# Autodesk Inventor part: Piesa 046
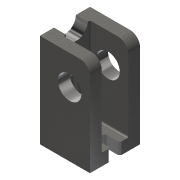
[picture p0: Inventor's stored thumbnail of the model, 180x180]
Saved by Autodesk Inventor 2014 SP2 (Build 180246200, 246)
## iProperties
Created: 2009-01
Part Number: Piesa 046
Document SubType Name: Modeling
Designer: Costel
Material: Steel, Cast
Density: 7.85 g/cm^3
Appearance: Steel - Cast
Mass: 2292.52 g
Surface Area: 500.17 cm^2
Volume: 292.041 cm^3
Author: Costel
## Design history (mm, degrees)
sketch "Sketch2"
  geometry: L1 (-32, 120)-(32, 120); L2 (32, 120)-(32, 0); L3 (32, 0)-(-32, 0); L4 (-32, 0)-(-32, 120); L5 (-38.4, 0)-(51.2, 0) reference; L6 (0, -12)-(0, 156) reference
  constraints: 8 end point, 2 parallel, 1 collinear, 1 horizontal, 1 perpendicular, 1 other
  dimensions: "d0" = 64 distance of L1.start L1.end; "d1" = 120 distance of L3.end L1.start
extrude "Extrusion1" new body sketch "Sketch2" distance "d2" = 15; taper "d3" = 0 deg
sketch "Sketch3"
  geometry: L1 (-120, 32)-(0, 32) reference; L2 (-120, -32)-(-120, 32) reference; L3 (0, -32)-(-120, -32) reference; L4 (0, 32)-(0, -32) reference; L5 (-120, 17)-(-15, 17); L6 (-15, 17)-(-15, -17); L7 (-15, -17)-(-120, -17); L8 (-120, -17)-(-120, -32); L9 (-120, -32)-(0, -32); L10 (0, -32)-(0, 32); L11 (0, 32)-(-120, 32); L12 (-120, 32)-(-120, 17); L13 (12, 0)-(-156, 0) reference
  constraints: 16 end point, 4 perpendicular, 2 point on line, 1 collinear, 1 other
  dimensions: "d4" = 34 distance between parallel lines of L5 L7; "d5" = 15 distance between parallel lines of L4 L6
extrude "Extrusion2" join sketch "Sketch3" distance "d6" = 49; taper "d7" = 0 deg
fillet "Fillet1" dims "d8" = 13
sketch "Sketch4"
  geometry: L1 (-120, -17)-(-120, 17) reference; L2 (12, 0)-(-156, 0) reference; C1 r 14 at (-120, 0)
  constraints: 1 centre point, 1 midpoint, 1 point on line
  dimensions: "d9" = 28 diameter of C1
extrude "Extrusion3" cut sketch "Sketch4" stored distance "d10" = 49; taper "d11" = 0 deg
sketch "Sketch5"
  geometry: L1 (0, -38.4)-(0, 51.2) reference; L2 (12, 0)-(-156, 0) reference; L3 (-15, -17)-(-15, 17) reference; L4 (-15, -5)-(-71.091, -5); L5 (-92.343, -6.084)-(-156, -6.084); L6 (-92.343, 6.084)-(-156, 6.084); L7 (12, 6.084)-(0, 6.084); L8 (-15, 5)-(-71.091, 5); L9 (-15, -5)-(-15, 5); A1 r 12 centre (-82, 0) between (-71.091, 5) and (-71.091, -5)
  constraints: 12 end point, 5 parallel, 4 point on circle, 4 point on line, 1 centre point, 1 collinear, 1 other
  dimensions: "d12" = 24 diameter of A1; "d15" = 10 distance between parallel lines of L8 L4; "d21" = 82 distance from line of L1 A1.centre
extrude "Extrusion4" join sketch "Sketch5" distance "d13" = 4; taper "d14" = 0 deg
sketch "Sketch6"
  geometry: L1 (-19, 70)-(-35, 15); L2 (-19, 71.091)-(-19, 15) reference; L3 (-15, 15)-(-64, 15) reference; L4 (-19, 71.091)-(-19, 94) reference; L5 (-15, 71.091)-(-15, 15) reference; L6 (-15, 15)-(-15, 120) reference; L7 (-15, 120)-(-15, 120) reference; L8 (-15, 120)-(-15, 15) reference; L9 (-15, 15)-(-15, 71.091) reference; L10 (-15, 71.091)-(-15, 71.091) reference; 1 further point
  constraints: 2 end point, 2 point on line
  dimensions: "d16" = 55 vertical distance of L1.start L1.end; "d20" = 20 distance from line of L5 L1.end
feature "Rib1" sketch "Sketch6" dims "d18" = 1, "d19" = 10
hole "Hole1" diameter "d24" = 14; stored, may be unused: countersink angle "d28" = 90 deg, drill point angle "d30" = 118 deg; dims "d22" = 10, "d23" = 10, "d25" = 6, "d26" = 4, "d27" = 2, "d29" = 8
hole "Hole2" diameter "d33" = 30; stored, may be unused: countersink angle "d37" = 90 deg, drill point angle "d39" = 118 deg; dims "d31" = 38, "d32" = 82, "d34" = 6, "d35" = 4, "d36" = 2, "d38" = 8
sketch "Sketch7"
  geometry: L1 (49, 0)-(49, 34) reference; L2 (-21.4, 17)-(68.2, 17) reference; L3 (34, 11)-(49, 11); L4 (34, 23)-(49, 23); L5 (49, 23)-(49, 11); A1 r 6 centre (34, 17) between (34, 23) and (34, 11)
  constraints: 6 end point, 3 point on line, 2 perpendicular, 2 point on circle, 2 tangent, 1 centre point, 1 collinear
  dimensions: "d40" = 12 diameter of A1; "d41" = 15 distance from line of L1 A1.centre
extrude "Extrusion5" cut sketch "Sketch7" stored distance "d42" = 4; taper "d43" = 0 deg
chamfer "Chamfer1" distance "d44" = 2; stored, may be unused: second distance "d45" = 2, angle "d46" = 45 deg
fillet "Fillet2" dims "d47" = 2
body "Solid1"
node "Projected Loop1"
